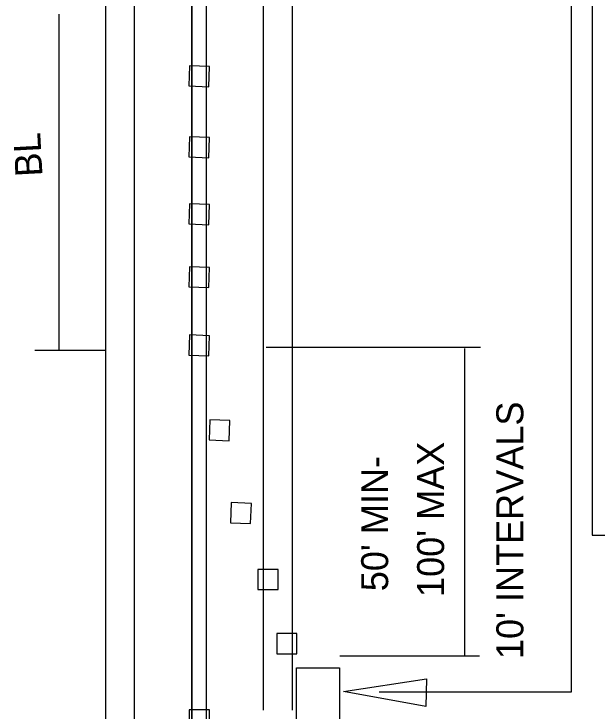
# Model space of a CAD drawing. Extents: x 21.7 to 29.1, y 5.9 to 16.2.
# Drawn here: x 24.497 to 25.794, y 11.205 to 12.755 of the extents above; entities that cross this region are included whole.
import ezdxf

# ---------------------------------------------------------------- set-up
doc = ezdxf.new("R2010")
doc.units = 0
for name, color, linetype in [('DETL-DIMS', 7, 'Continuous'), ('DETL-LINE', 7, 'Continuous'), ('DETL-NOTE', 7, 'Continuous')]:
    doc.layers.add(name, color=color, linetype=linetype)

msp = doc.modelspace()

# ---------------------------------------------------------------- linework, layer by layer
at = {"layer": 'DETL-DIMS'}
for p, q in [((24.5972, 12.7548), (24.5972, 12.0071)), ((24.5438, 12.0071), (24.6992, 12.0071)), ((25.058, 12.0137), (25.5344, 12.0137)), ((25.4992, 12.0114), (25.4992, 11.3272)), ((25.2214, 11.3272), (25.5322, 11.3272)), ((25.3088, 11.2472), (25.7359, 11.2472))]:
    msp.add_line(p, q, dxfattribs=at)
msp.add_lwpolyline([(25.4143, 11.2765), (25.4131, 11.215), (25.2299, 11.2484)], close=True, dxfattribs=at)
at = {"layer": 'DETL-LINE'}
for p, q in [((24.8927, 7.7401), (24.8927, 15.6283)), ((24.7011, 9.2959), (24.7011, 15.5751)), ((24.7651, 9.2959), (24.7651, 15.5751)), ((24.893, 9.2959), (24.893, 15.5751)), ((24.9252, 9.2959), (24.9252, 15.5751)), ((25.0521, 11.2067), (25.0521, 15.5751)), ((25.1164, 11.2067), (25.1164, 15.5751)), ((24.9252, 7.7401), (24.9252, 15.5547)), ((25.7357, 12.9882), (25.7357, 11.247))]:
    msp.add_line(p, q, dxfattribs=at)
for points in [[(25.7831, 11.5962), (29.0092, 11.5962), (29.0092, 14.3652), (25.7831, 14.3652)], [(24.9305, 12.5932), (24.9322, 12.6379), (24.8874, 12.6398), (24.8857, 12.595)], [(24.9305, 12.4353), (24.9322, 12.4801), (24.8874, 12.4819), (24.8857, 12.4371)], [(24.9305, 12.2864), (24.9322, 12.3311), (24.8874, 12.333), (24.8857, 12.2882)], [(24.9305, 12.1464), (24.9322, 12.1911), (24.8874, 12.193), (24.8857, 12.1482)], [(24.9305, 11.9945), (24.9322, 12.0392), (24.8874, 12.0411), (24.8857, 11.9963)], [(24.9757, 11.8058), (24.9774, 11.8506), (24.9326, 11.8524), (24.9309, 11.8076)], [(25.0233, 11.6216), (25.025, 11.6663), (24.9803, 11.6682), (24.9786, 11.6234)], [(25.0396, 11.4747), (25.0844, 11.4747), (25.0844, 11.5195), (25.0396, 11.5195)], [(25.0815, 11.3322), (25.1263, 11.3322), (25.1263, 11.377), (25.0815, 11.377)], [(25.1252, 11.1381), (25.1252, 11.3006), (25.2207, 11.3006), (25.2207, 11.1381)], [(24.887, 11.1626), (24.9318, 11.1626), (24.9318, 11.2074), (24.887, 11.2074)]]:
    msp.add_lwpolyline(points, close=True, dxfattribs=at)

# ---------------------------------------------------------------- texts
at = {"layer": 'DETL-NOTE'}
for s, rotation, p in [('BL', 93.0746, (24.5606, 12.3946)), ("10' INTERVALS", 90, (25.6297, 11.3203)), ("100' MAX", 90, (25.4535, 11.4584)), ("50' MIN-", 90, (25.3291, 11.4712))]:
    msp.add_text(s, height=0.06, rotation=rotation, dxfattribs=at).set_placement(p)

doc.saveas('drawing.dxf')
